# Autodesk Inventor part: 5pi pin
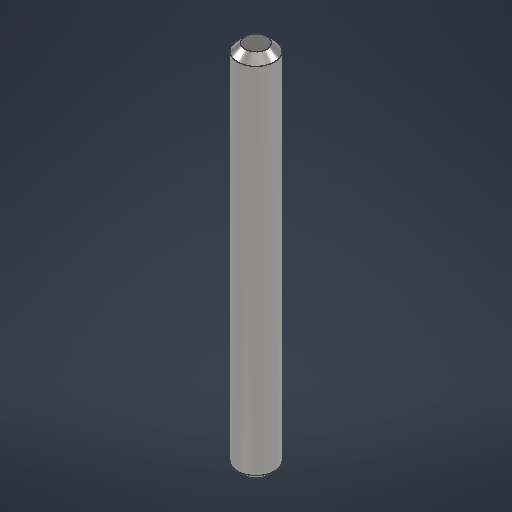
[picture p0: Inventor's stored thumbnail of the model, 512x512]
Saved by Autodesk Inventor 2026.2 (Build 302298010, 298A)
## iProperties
Created: 2026-04
Part Number: 5pi pin
Material: 스테인리스스틸
Document SubType Name: Modeling
Designer: work
Density: 8 g/cm^3
Appearance: 반연마
Author: work
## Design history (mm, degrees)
sketch "스케치1"
  geometry: C1 r 2.5 at (0, 0); 1 further point
  constraints: 1 centre point, 1 coincident
  dimensions: "d0" = 5 diameter of C1
extrude "돌출1" new body sketch "스케치1" distance "d1" = 50; taper "d2" = 0 deg
chamfer "모따기1" distance "d3" = 1; stored, may be unused: second distance "d4" = 2, angle "d5" = 45 deg
node "솔리드1"
